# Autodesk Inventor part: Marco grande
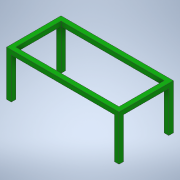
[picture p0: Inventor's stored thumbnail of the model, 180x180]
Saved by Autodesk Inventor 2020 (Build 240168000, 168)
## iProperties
Created: 2019-03
Part Number: Marco grande
Material: Generic
Document SubType Name: Modeling
Designer: user
Density: 1 g/cm^3
Appearance: Default
Author: user
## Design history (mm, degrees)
derived "Marco grande.iam"
body "Solid1"
node "Frame0001.iam:1::Skeleton0001.ipt:1"
node "Frame0001.iam:1::ANSI 1x1 00000001:1"
node "Frame0001.iam:1::ANSI 1x1 00000002:1"
node "Frame0001.iam:1::ANSI 1x1 00000003:1"
node "Frame0001.iam:1::ANSI 1x1 00000004:1"
node "Frame0001.iam:1::ANSI 1x1 00000005:1"
node "Frame0001.iam:1::ANSI 1x1 00000006:1"
node "Frame0001.iam:1::ANSI 1x1 00000007:1"
node "Frame0001.iam:1::ANSI 1x1 00000008:1"
